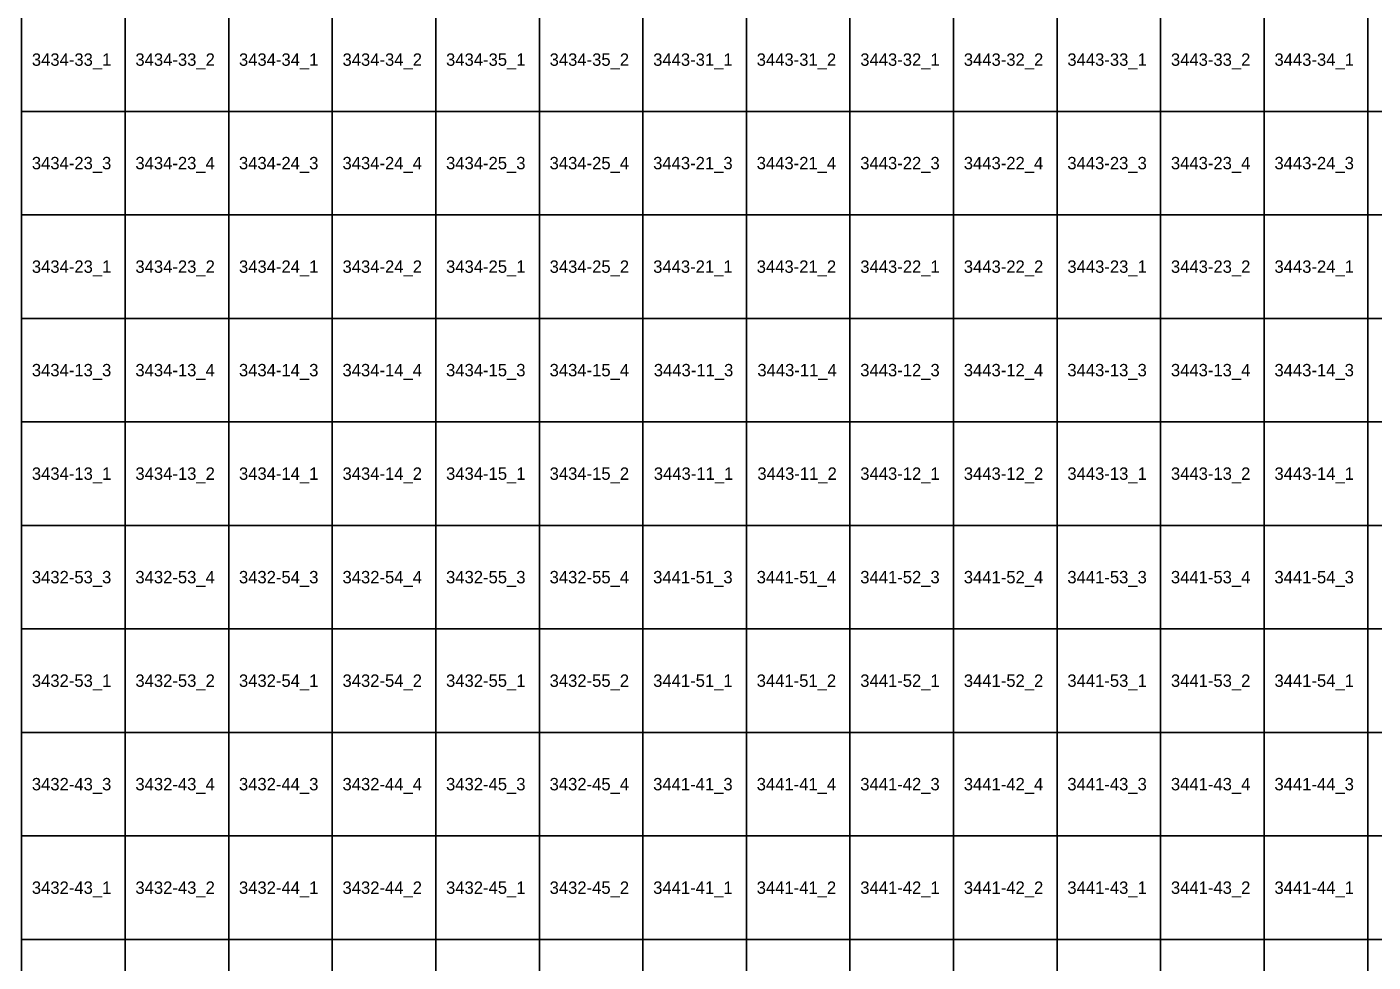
# Model space of a CAD drawing. Extents: x 312500 to 765000, y 172500 to 440000.
# Drawn here: x 635129 to 667629, y 264452 to 287039 of the extents above; entities that cross this region are included whole.
import ezdxf

# ---------------------------------------------------------------- set-up
doc = ezdxf.new("R2010")
doc.units = 0
doc.layers.add('Topo5_ramis_TKS2025', color=7, linetype='Continuous')
doc.layers.add('Topo5_ramis_TKS2025_Nr', color=7, linetype='Continuous')

msp = doc.modelspace()

# ---------------------------------------------------------------- linework, layer by layer
at = {"layer": 'Topo5_ramis_TKS2025'}
for points in [[(635000, 285000), (635000, 287500), (637500, 287500), (637500, 285000), (635000, 285000)], [(637500, 285000), (637500, 287500), (640000, 287500), (640000, 285000), (637500, 285000)], [(640000, 285000), (640000, 287500), (642500, 287500), (642500, 285000), (640000, 285000)], [(642500, 285000), (642500, 287500), (645000, 287500), (645000, 285000), (642500, 285000)], [(645000, 285000), (645000, 287500), (647500, 287500), (647500, 285000), (645000, 285000)], [(647500, 285000), (647500, 287500), (650000, 287500), (650000, 285000), (647500, 285000)], [(650000, 285000), (650000, 287500), (652500, 287500), (652500, 285000), (650000, 285000)], [(652500, 285000), (652500, 287500), (655000, 287500), (655000, 285000), (652500, 285000)], [(655000, 285000), (655000, 287500), (657500, 287500), (657500, 285000), (655000, 285000)], [(657500, 285000), (657500, 287500), (660000, 287500), (660000, 285000), (657500, 285000)], [(660000, 285000), (660000, 287500), (662500, 287500), (662500, 285000), (660000, 285000)], [(662500, 285000), (662500, 287500), (665000, 287500), (665000, 285000), (662500, 285000)], [(665000, 285000), (665000, 287500), (667500, 287500), (667500, 285000), (665000, 285000)], [(667500, 285000), (667500, 287500), (670000, 287500), (670000, 285000), (667500, 285000)], [(635000, 282500), (635000, 285000), (637500, 285000), (637500, 282500), (635000, 282500)], [(637500, 282500), (637500, 285000), (640000, 285000), (640000, 282500), (637500, 282500)], [(640000, 282500), (640000, 285000), (642500, 285000), (642500, 282500), (640000, 282500)], [(642500, 282500), (642500, 285000), (645000, 285000), (645000, 282500), (642500, 282500)], [(645000, 282500), (645000, 285000), (647500, 285000), (647500, 282500), (645000, 282500)], [(647500, 282500), (647500, 285000), (650000, 285000), (650000, 282500), (647500, 282500)], [(650000, 282500), (650000, 285000), (652500, 285000), (652500, 282500), (650000, 282500)], [(652500, 282500), (652500, 285000), (655000, 285000), (655000, 282500), (652500, 282500)], [(655000, 282500), (655000, 285000), (657500, 285000), (657500, 282500), (655000, 282500)], [(657500, 282500), (657500, 285000), (660000, 285000), (660000, 282500), (657500, 282500)], [(660000, 282500), (660000, 285000), (662500, 285000), (662500, 282500), (660000, 282500)], [(662500, 282500), (662500, 285000), (665000, 285000), (665000, 282500), (662500, 282500)], [(665000, 282500), (665000, 285000), (667500, 285000), (667500, 282500), (665000, 282500)], [(667500, 282500), (667500, 285000), (670000, 285000), (670000, 282500), (667500, 282500)], [(635000, 280000), (635000, 282500), (637500, 282500), (637500, 280000), (635000, 280000)], [(637500, 280000), (637500, 282500), (640000, 282500), (640000, 280000), (637500, 280000)], [(640000, 280000), (640000, 282500), (642500, 282500), (642500, 280000), (640000, 280000)], [(642500, 280000), (642500, 282500), (645000, 282500), (645000, 280000), (642500, 280000)], [(645000, 280000), (645000, 282500), (647500, 282500), (647500, 280000), (645000, 280000)], [(647500, 280000), (647500, 282500), (650000, 282500), (650000, 280000), (647500, 280000)], [(650000, 280000), (650000, 282500), (652500, 282500), (652500, 280000), (650000, 280000)], [(652500, 280000), (652500, 282500), (655000, 282500), (655000, 280000), (652500, 280000)], [(655000, 280000), (655000, 282500), (657500, 282500), (657500, 280000), (655000, 280000)], [(657500, 280000), (657500, 282500), (660000, 282500), (660000, 280000), (657500, 280000)], [(660000, 280000), (660000, 282500), (662500, 282500), (662500, 280000), (660000, 280000)], [(662500, 280000), (662500, 282500), (665000, 282500), (665000, 280000), (662500, 280000)], [(665000, 280000), (665000, 282500), (667500, 282500), (667500, 280000), (665000, 280000)], [(667500, 280000), (667500, 282500), (670000, 282500), (670000, 280000), (667500, 280000)], [(635000, 277500), (635000, 280000), (637500, 280000), (637500, 277500), (635000, 277500)], [(637500, 277500), (637500, 280000), (640000, 280000), (640000, 277500), (637500, 277500)], [(640000, 277500), (640000, 280000), (642500, 280000), (642500, 277500), (640000, 277500)], [(642500, 277500), (642500, 280000), (645000, 280000), (645000, 277500), (642500, 277500)], [(645000, 277500), (645000, 280000), (647500, 280000), (647500, 277500), (645000, 277500)], [(647500, 277500), (647500, 280000), (650000, 280000), (650000, 277500), (647500, 277500)], [(650000, 277500), (650000, 280000), (652500, 280000), (652500, 277500), (650000, 277500)], [(652500, 277500), (652500, 280000), (655000, 280000), (655000, 277500), (652500, 277500)], [(655000, 277500), (655000, 280000), (657500, 280000), (657500, 277500), (655000, 277500)], [(657500, 277500), (657500, 280000), (660000, 280000), (660000, 277500), (657500, 277500)], [(660000, 277500), (660000, 280000), (662500, 280000), (662500, 277500), (660000, 277500)], [(662500, 277500), (662500, 280000), (665000, 280000), (665000, 277500), (662500, 277500)], [(665000, 277500), (665000, 280000), (667500, 280000), (667500, 277500), (665000, 277500)], [(667500, 277500), (667500, 280000), (670000, 280000), (670000, 277500), (667500, 277500)], [(635000, 275000), (635000, 277500), (637500, 277500), (637500, 275000), (635000, 275000)], [(637500, 275000), (637500, 277500), (640000, 277500), (640000, 275000), (637500, 275000)], [(640000, 275000), (640000, 277500), (642500, 277500), (642500, 275000), (640000, 275000)], [(642500, 275000), (642500, 277500), (645000, 277500), (645000, 275000), (642500, 275000)], [(645000, 275000), (645000, 277500), (647500, 277500), (647500, 275000), (645000, 275000)], [(647500, 275000), (647500, 277500), (650000, 277500), (650000, 275000), (647500, 275000)], [(650000, 275000), (650000, 277500), (652500, 277500), (652500, 275000), (650000, 275000)], [(652500, 275000), (652500, 277500), (655000, 277500), (655000, 275000), (652500, 275000)], [(655000, 275000), (655000, 277500), (657500, 277500), (657500, 275000), (655000, 275000)], [(657500, 275000), (657500, 277500), (660000, 277500), (660000, 275000), (657500, 275000)], [(660000, 275000), (660000, 277500), (662500, 277500), (662500, 275000), (660000, 275000)], [(662500, 275000), (662500, 277500), (665000, 277500), (665000, 275000), (662500, 275000)], [(665000, 275000), (665000, 277500), (667500, 277500), (667500, 275000), (665000, 275000)], [(667500, 275000), (667500, 277500), (670000, 277500), (670000, 275000), (667500, 275000)], [(635000, 272500), (635000, 275000), (637500, 275000), (637500, 272500), (635000, 272500)], [(637500, 272500), (637500, 275000), (640000, 275000), (640000, 272500), (637500, 272500)], [(640000, 272500), (640000, 275000), (642500, 275000), (642500, 272500), (640000, 272500)], [(642500, 272500), (642500, 275000), (645000, 275000), (645000, 272500), (642500, 272500)], [(645000, 272500), (645000, 275000), (647500, 275000), (647500, 272500), (645000, 272500)], [(647500, 272500), (647500, 275000), (650000, 275000), (650000, 272500), (647500, 272500)], [(650000, 272500), (650000, 275000), (652500, 275000), (652500, 272500), (650000, 272500)], [(652500, 272500), (652500, 275000), (655000, 275000), (655000, 272500), (652500, 272500)], [(655000, 272500), (655000, 275000), (657500, 275000), (657500, 272500), (655000, 272500)], [(657500, 272500), (657500, 275000), (660000, 275000), (660000, 272500), (657500, 272500)], [(660000, 272500), (660000, 275000), (662500, 275000), (662500, 272500), (660000, 272500)], [(662500, 272500), (662500, 275000), (665000, 275000), (665000, 272500), (662500, 272500)], [(665000, 272500), (665000, 275000), (667500, 275000), (667500, 272500), (665000, 272500)], [(667500, 272500), (667500, 275000), (670000, 275000), (670000, 272500), (667500, 272500)], [(635000, 270000), (635000, 272500), (637500, 272500), (637500, 270000), (635000, 270000)], [(637500, 270000), (637500, 272500), (640000, 272500), (640000, 270000), (637500, 270000)], [(640000, 270000), (640000, 272500), (642500, 272500), (642500, 270000), (640000, 270000)], [(642500, 270000), (642500, 272500), (645000, 272500), (645000, 270000), (642500, 270000)], [(645000, 270000), (645000, 272500), (647500, 272500), (647500, 270000), (645000, 270000)], [(647500, 270000), (647500, 272500), (650000, 272500), (650000, 270000), (647500, 270000)], [(650000, 270000), (650000, 272500), (652500, 272500), (652500, 270000), (650000, 270000)], [(652500, 270000), (652500, 272500), (655000, 272500), (655000, 270000), (652500, 270000)], [(655000, 270000), (655000, 272500), (657500, 272500), (657500, 270000), (655000, 270000)], [(657500, 270000), (657500, 272500), (660000, 272500), (660000, 270000), (657500, 270000)], [(660000, 270000), (660000, 272500), (662500, 272500), (662500, 270000), (660000, 270000)], [(662500, 270000), (662500, 272500), (665000, 272500), (665000, 270000), (662500, 270000)], [(665000, 270000), (665000, 272500), (667500, 272500), (667500, 270000), (665000, 270000)], [(667500, 270000), (667500, 272500), (670000, 272500), (670000, 270000), (667500, 270000)], [(635000, 267500), (635000, 270000), (637500, 270000), (637500, 267500), (635000, 267500)], [(637500, 267500), (637500, 270000), (640000, 270000), (640000, 267500), (637500, 267500)], [(640000, 267500), (640000, 270000), (642500, 270000), (642500, 267500), (640000, 267500)], [(642500, 267500), (642500, 270000), (645000, 270000), (645000, 267500), (642500, 267500)], [(645000, 267500), (645000, 270000), (647500, 270000), (647500, 267500), (645000, 267500)], [(647500, 267500), (647500, 270000), (650000, 270000), (650000, 267500), (647500, 267500)], [(650000, 267500), (650000, 270000), (652500, 270000), (652500, 267500), (650000, 267500)], [(652500, 267500), (652500, 270000), (655000, 270000), (655000, 267500), (652500, 267500)], [(655000, 267500), (655000, 270000), (657500, 270000), (657500, 267500), (655000, 267500)], [(657500, 267500), (657500, 270000), (660000, 270000), (660000, 267500), (657500, 267500)], [(660000, 267500), (660000, 270000), (662500, 270000), (662500, 267500), (660000, 267500)], [(662500, 267500), (662500, 270000), (665000, 270000), (665000, 267500), (662500, 267500)], [(665000, 267500), (665000, 270000), (667500, 270000), (667500, 267500), (665000, 267500)], [(667500, 267500), (667500, 270000), (670000, 270000), (670000, 267500), (667500, 267500)], [(635000, 265000), (635000, 267500), (637500, 267500), (637500, 265000), (635000, 265000)], [(637500, 265000), (637500, 267500), (640000, 267500), (640000, 265000), (637500, 265000)], [(640000, 265000), (640000, 267500), (642500, 267500), (642500, 265000), (640000, 265000)], [(642500, 265000), (642500, 267500), (645000, 267500), (645000, 265000), (642500, 265000)], [(645000, 265000), (645000, 267500), (647500, 267500), (647500, 265000), (645000, 265000)], [(647500, 265000), (647500, 267500), (650000, 267500), (650000, 265000), (647500, 265000)], [(650000, 265000), (650000, 267500), (652500, 267500), (652500, 265000), (650000, 265000)], [(652500, 265000), (652500, 267500), (655000, 267500), (655000, 265000), (652500, 265000)], [(655000, 265000), (655000, 267500), (657500, 267500), (657500, 265000), (655000, 265000)], [(657500, 265000), (657500, 267500), (660000, 267500), (660000, 265000), (657500, 265000)], [(660000, 265000), (660000, 267500), (662500, 267500), (662500, 265000), (660000, 265000)], [(662500, 265000), (662500, 267500), (665000, 267500), (665000, 265000), (662500, 265000)], [(665000, 265000), (665000, 267500), (667500, 267500), (667500, 265000), (665000, 265000)], [(667500, 265000), (667500, 267500), (670000, 267500), (670000, 265000), (667500, 265000)], [(635000, 262500), (635000, 265000), (637500, 265000), (637500, 262500), (635000, 262500)], [(637500, 262500), (637500, 265000), (640000, 265000), (640000, 262500), (637500, 262500)], [(640000, 262500), (640000, 265000), (642500, 265000), (642500, 262500), (640000, 262500)], [(642500, 262500), (642500, 265000), (645000, 265000), (645000, 262500), (642500, 262500)], [(645000, 262500), (645000, 265000), (647500, 265000), (647500, 262500), (645000, 262500)], [(647500, 262500), (647500, 265000), (650000, 265000), (650000, 262500), (647500, 262500)], [(650000, 262500), (650000, 265000), (652500, 265000), (652500, 262500), (650000, 262500)], [(652500, 262500), (652500, 265000), (655000, 265000), (655000, 262500), (652500, 262500)], [(655000, 262500), (655000, 265000), (657500, 265000), (657500, 262500), (655000, 262500)], [(657500, 262500), (657500, 265000), (660000, 265000), (660000, 262500), (657500, 262500)], [(660000, 262500), (660000, 265000), (662500, 265000), (662500, 262500), (660000, 262500)], [(662500, 262500), (662500, 265000), (665000, 265000), (665000, 262500), (662500, 262500)], [(665000, 262500), (665000, 265000), (667500, 265000), (667500, 262500), (665000, 262500)], [(667500, 262500), (667500, 265000), (670000, 265000), (670000, 262500), (667500, 262500)]]:
    msp.add_lwpolyline(points, dxfattribs=at)

# ---------------------------------------------------------------- texts
at = {"layer": 'Topo5_ramis_TKS2025_Nr'}
for s, p in [('3434-33_1', (635248, 286100)), ('3434-33_2', (637748, 286100)), ('3434-34_1', (640248, 286100)), ('3434-34_2', (642748, 286100)), ('3434-35_1', (645248, 286100)), ('3434-35_2', (647748, 286100)), ('3443-31_1', (650248, 286100)), ('3443-31_2', (652748, 286100)), ('3443-32_1', (655248, 286100)), ('3443-32_2', (657748, 286100)), ('3443-33_1', (660248, 286100)), ('3443-33_2', (662748, 286100)), ('3443-34_1', (665248, 286100)), ('3434-23_3', (635248, 283600)), ('3434-23_4', (637748, 283600)), ('3434-24_3', (640248, 283600)), ('3434-24_4', (642748, 283600)), ('3434-25_3', (645248, 283600)), ('3434-25_4', (647748, 283600)), ('3443-21_3', (650248, 283600)), ('3443-21_4', (652748, 283600)), ('3443-22_3', (655248, 283600)), ('3443-22_4', (657748, 283600)), ('3443-23_3', (660248, 283600)), ('3443-23_4', (662748, 283600)), ('3443-24_3', (665248, 283600)), ('3434-23_1', (635248, 281100)), ('3434-23_2', (637748, 281100)), ('3434-24_1', (640248, 281100)), ('3434-24_2', (642748, 281100)), ('3434-25_1', (645248, 281100)), ('3434-25_2', (647748, 281100)), ('3443-21_1', (650248, 281100)), ('3443-21_2', (652748, 281100)), ('3443-22_1', (655248, 281100)), ('3443-22_2', (657748, 281100)), ('3443-23_1', (660248, 281100)), ('3443-23_2', (662748, 281100)), ('3443-24_1', (665248, 281100)), ('3434-13_3', (635248, 278600)), ('3434-13_4', (637748, 278600)), ('3434-14_3', (640248, 278600)), ('3434-14_4', (642748, 278600)), ('3434-15_3', (645248, 278600)), ('3434-15_4', (647748, 278600)), ('3443-11_3', (650264, 278600)), ('3443-11_4', (652764, 278600)), ('3443-12_3', (655248, 278600)), ('3443-12_4', (657748, 278600)), ('3443-13_3', (660248, 278600)), ('3443-13_4', (662748, 278600)), ('3443-14_3', (665248, 278600)), ('3434-13_1', (635248, 276100)), ('3434-13_2', (637748, 276100)), ('3434-14_1', (640248, 276100)), ('3434-14_2', (642748, 276100)), ('3434-15_1', (645248, 276100)), ('3434-15_2', (647748, 276100)), ('3443-11_1', (650264, 276100)), ('3443-11_2', (652764, 276100)), ('3443-12_1', (655248, 276100)), ('3443-12_2', (657748, 276100)), ('3443-13_1', (660248, 276100)), ('3443-13_2', (662748, 276100)), ('3443-14_1', (665248, 276100)), ('3432-53_3', (635248, 273600)), ('3432-53_4', (637748, 273600)), ('3432-54_3', (640248, 273600)), ('3432-54_4', (642748, 273600)), ('3432-55_3', (645248, 273600)), ('3432-55_4', (647748, 273600)), ('3441-51_3', (650248, 273600)), ('3441-51_4', (652748, 273600)), ('3441-52_3', (655248, 273600)), ('3441-52_4', (657748, 273600)), ('3441-53_3', (660248, 273600)), ('3441-53_4', (662748, 273600)), ('3441-54_3', (665248, 273600)), ('3432-53_1', (635248, 271100)), ('3432-53_2', (637748, 271100)), ('3432-54_1', (640248, 271100)), ('3432-54_2', (642748, 271100)), ('3432-55_1', (645248, 271100)), ('3432-55_2', (647748, 271100)), ('3441-51_1', (650248, 271100)), ('3441-51_2', (652748, 271100)), ('3441-52_1', (655248, 271100)), ('3441-52_2', (657748, 271100)), ('3441-53_1', (660248, 271100)), ('3441-53_2', (662748, 271100)), ('3441-54_1', (665248, 271100)), ('3432-43_3', (635248, 268600)), ('3432-43_4', (637748, 268600)), ('3432-44_3', (640248, 268600)), ('3432-44_4', (642748, 268600)), ('3432-45_3', (645248, 268600)), ('3432-45_4', (647748, 268600)), ('3441-41_3', (650248, 268600)), ('3441-41_4', (652748, 268600)), ('3441-42_3', (655248, 268600)), ('3441-42_4', (657748, 268600)), ('3441-43_3', (660248, 268600)), ('3441-43_4', (662748, 268600)), ('3441-44_3', (665248, 268600)), ('3432-43_1', (635248, 266100)), ('3432-43_2', (637748, 266100)), ('3432-44_1', (640248, 266100)), ('3432-44_2', (642748, 266100)), ('3432-45_1', (645248, 266100)), ('3432-45_2', (647748, 266100)), ('3441-41_1', (650248, 266100)), ('3441-41_2', (652748, 266100)), ('3441-42_1', (655248, 266100)), ('3441-42_2', (657748, 266100)), ('3441-43_1', (660248, 266100)), ('3441-43_2', (662748, 266100)), ('3441-44_1', (665248, 266100))]:
    msp.add_text(s, height=300, dxfattribs=at).set_placement(p)

doc.saveas('drawing.dxf')
